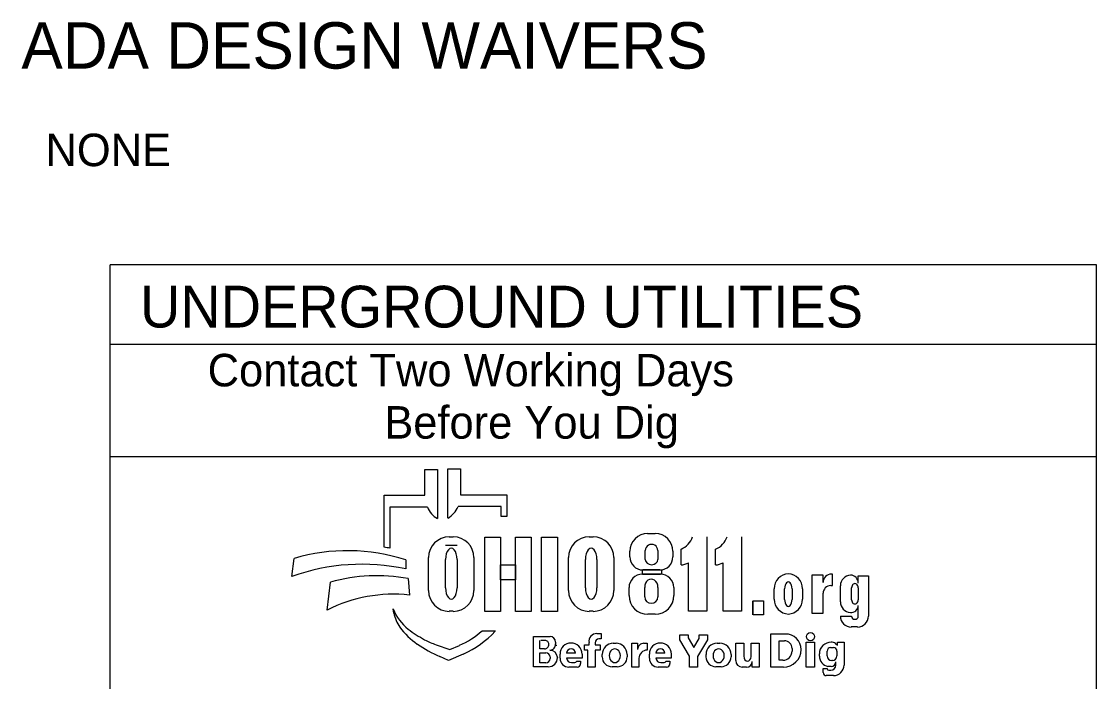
# Model space of a CAD drawing. Extents: x -31.7 to 34, y 0 to 22.
# Drawn here: x -31.252 to -26.619, y 2.686 to 5.529 of the extents above; entities that cross this region are included whole.
import ezdxf

# ---------------------------------------------------------------- set-up
doc = ezdxf.new("R2010")
doc.units = 0
doc.layers.add('SH_Data', color=7, linetype='Continuous')
doc.layers.add('SH_Text', color=7, linetype='Continuous')

msp = doc.modelspace()

# ---------------------------------------------------------------- linework, layer by layer
at = {"layer": 'SH_Data'}
for p, q in [((-30.8694, 2.1428), (-30.8694, 4.4803)), ((-26.6194, 4.4803), (-30.8694, 4.4803)), ((-26.6194, 2.1428), (-26.6194, 4.4803)), ((-30.8694, 4.1387), (-26.6194, 4.1387)), ((-30.8694, 3.6553), (-26.6194, 3.6553))]:
    msp.add_line(p, q, dxfattribs=at)
at = {"layer": 'SH_Text'}
for p, q in [((-29.5133, 3.4883), (-29.5133, 3.5998)), ((-29.5133, 3.5998), (-29.4597, 3.5998)), ((-29.4597, 3.5998), (-29.4597, 3.3877)), ((-29.414, 3.39), (-29.414, 3.6021)), ((-29.414, 3.6021), (-29.3604, 3.6021)), ((-29.3604, 3.6021), (-29.3604, 3.4906)), ((-29.6893, 3.2644), (-29.6893, 3.4883)), ((-29.6893, 3.4883), (-29.5133, 3.4883)), ((-29.3604, 3.4906), (-29.1611, 3.4906)), ((-29.1611, 3.4906), (-29.1611, 3.3968)), ((-29.664, 3.4369), (-29.664, 3.26)), ((-29.5029, 3.4369), (-29.664, 3.4369)), ((-29.1844, 3.4392), (-29.3708, 3.4392)), ((-29.1844, 3.3968), (-29.1844, 3.4392)), ((-29.1611, 3.3968), (-29.1844, 3.3968)), ((-29.4083, 3.3091), (-29.3918, 3.3091)), ((-28.8053, 3.3091), (-28.7888, 3.3091)), ((-28.5538, 3.3231), (-28.521, 3.3231)), ((-28.2982, 3.3087), (-28.2982, 2.9887)), ((-28.1494, 3.3087), (-28.1494, 2.9887)), ((-29.3751, 3.2721), (-29.4249, 3.2721)), ((-28.6301, 3.2225), (-28.6301, 3.2468)), ((-28.5639, 3.2111), (-28.5639, 3.2504)), ((-28.5098, 3.2504), (-28.5098, 3.2111)), ((-28.4447, 3.2468), (-28.4447, 3.2225)), ((-28.4098, 3.188), (-28.4098, 3.2562)), ((-28.261, 3.188), (-28.261, 3.2562)), ((-30.0866, 3.1381), (-30.0773, 3.2162)), ((-29.596, 3.2097), (-29.596, 3.1709)), ((-29.4978, 3.0776), (-29.4978, 3.2196)), ((-29.4249, 3.089), (-29.4249, 3.2114)), ((-29.3751, 3.2114), (-29.3751, 3.089)), ((-29.3023, 3.2196), (-29.3023, 3.0776)), ((-28.8948, 3.0776), (-28.8948, 3.2196)), ((-28.8219, 3.089), (-28.8219, 3.2114)), ((-28.7721, 3.2114), (-28.7721, 3.089)), ((-28.6993, 3.2196), (-28.6993, 3.0776)), ((-28.3775, 2.9887), (-28.3775, 3.1973)), ((-28.2287, 2.9887), (-28.2287, 3.1973)), ((-28.5007, 3.1665), (-28.5741, 3.1665)), ((-29.9348, 2.9936), (-29.9201, 3.1137)), ((-29.586, 3.1291), (-29.5798, 3.0582)), ((-28.5759, 3.1482), (-28.4986, 3.1482)), ((-27.7975, 3.1436), (-27.8464, 3.1436)), ((-27.8464, 3.1436), (-27.8464, 2.9806)), ((-27.7975, 3.112), (-27.7975, 3.1436)), ((-27.7569, 3.1487), (-27.7608, 3.1487)), ((-27.7569, 3.0989), (-27.7569, 3.1487)), ((-27.646, 3.1094), (-27.646, 3.1404)), ((-27.646, 3.1404), (-27.6025, 3.1404)), ((-27.6025, 3.1404), (-27.6025, 2.9675)), ((-28.6338, 3.0563), (-28.6338, 3.0903)), ((-28.5663, 3.0503), (-28.5663, 3.0912)), ((-28.5094, 3.0912), (-28.5094, 3.0503)), ((-28.4407, 3.0903), (-28.4407, 3.0563)), ((-28.0084, 3.0404), (-28.0084, 3.0858)), ((-27.9634, 3.0396), (-27.9634, 3.0858)), ((-27.9312, 3.0858), (-27.9312, 3.0396)), ((-27.8862, 3.0858), (-27.8862, 3.0404)), ((-27.7975, 2.9806), (-27.7975, 3.0659)), ((-27.7646, 3.0989), (-27.7569, 3.0989)), ((-27.7229, 3.029), (-27.7229, 3.0986)), ((-27.6746, 3.0383), (-27.6746, 3.0893)), ((-27.646, 3.0893), (-27.646, 3.0383)), ((-28.1013, 3.0337), (-28.1013, 2.9737)), ((-27.646, 2.9675), (-27.646, 3.0139)), ((-29.6471, 2.9807), (-29.6502, 2.9986)), ((-29.3918, 2.9882), (-29.4083, 2.9882)), ((-28.7888, 2.9882), (-28.8053, 2.9882)), ((-28.5216, 2.9753), (-28.5528, 2.9753)), ((-28.2982, 2.9887), (-28.3775, 2.9887)), ((-28.1494, 2.9887), (-28.2287, 2.9887)), ((-27.8464, 2.9806), (-27.7975, 2.9806)), ((-27.7229, 2.9675), (-27.6746, 2.9675)), ((-27.6492, 2.9208), (-27.6762, 2.9208)), ((-29.2668, 2.9048), (-29.2094, 2.9048)), ((-29.0455, 2.749), (-29.0455, 2.8798)), ((-29.0455, 2.8798), (-28.9744, 2.8798)), ((-28.773, 2.8926), (-28.7535, 2.8926)), ((-28.7535, 2.8926), (-28.7535, 2.8696)), ((-28.415, 2.887), (-28.3791, 2.887)), ((-28.415, 2.8655), (-28.415, 2.887)), ((-28.3791, 2.887), (-28.3791, 2.8734)), ((-28.3791, 2.8734), (-28.355, 2.832)), ((-28.3318, 2.8719), (-28.3318, 2.887)), ((-28.3318, 2.887), (-28.296, 2.887)), ((-28.296, 2.887), (-28.296, 2.8655)), ((-28.0225, 2.8906), (-27.9602, 2.8906)), ((-28.0225, 2.7478), (-28.0225, 2.8906)), ((-29.4653, 2.8444), (-29.4058, 2.8239)), ((-29.4058, 2.8239), (-29.3648, 2.8417)), ((-29.0176, 2.8263), (-29.0176, 2.8632)), ((-28.9982, 2.8263), (-29.0176, 2.8263)), ((-28.9924, 2.8632), (-29.0136, 2.8632)), ((-28.9506, 2.856), (-28.9506, 2.8481)), ((-28.8256, 2.8212), (-28.8256, 2.8442)), ((-28.8256, 2.8442), (-28.8062, 2.8442)), ((-28.8062, 2.8442), (-28.8062, 2.8546)), ((-28.7801, 2.8526), (-28.7801, 2.8442)), ((-28.7801, 2.8442), (-28.7586, 2.8442)), ((-28.7535, 2.8691), (-28.7637, 2.8691)), ((-28.7586, 2.8442), (-28.7586, 2.8212)), ((-28.7017, 2.8508), (-28.6896, 2.8508)), ((-28.6215, 2.7478), (-28.6215, 2.8505)), ((-28.6215, 2.8505), (-28.5969, 2.8505)), ((-28.5969, 2.8505), (-28.5969, 2.8237)), ((-28.5697, 2.8505), (-28.5558, 2.8505)), ((-28.5558, 2.8505), (-28.5558, 2.8209)), ((-28.3737, 2.7946), (-28.415, 2.8655)), ((-28.355, 2.832), (-28.3318, 2.8719)), ((-28.296, 2.8655), (-28.3381, 2.7932)), ((-28.2543, 2.8508), (-28.2422, 2.8508)), ((-28.1742, 2.8508), (-28.1394, 2.8508)), ((-28.1742, 2.7762), (-28.1742, 2.8508)), ((-28.1394, 2.8508), (-28.1394, 2.7954)), ((-28.108, 2.7938), (-28.108, 2.8508)), ((-28.108, 2.8508), (-28.0733, 2.8508)), ((-28.0733, 2.8508), (-28.0733, 2.7478)), ((-27.9865, 2.7773), (-27.9865, 2.8613)), ((-27.9865, 2.8613), (-27.9641, 2.8613)), ((-27.9314, 2.8286), (-27.9314, 2.8168)), ((-27.8699, 2.8549), (-27.8343, 2.8549)), ((-27.8699, 2.7478), (-27.8699, 2.8549)), ((-27.8343, 2.8549), (-27.8343, 2.7478)), ((-27.7653, 2.8319), (-27.7525, 2.8319)), ((-27.7447, 2.8493), (-27.7362, 2.8427)), ((-27.7362, 2.8553), (-27.7074, 2.8553)), ((-27.7362, 2.8427), (-27.7362, 2.8553)), ((-27.7362, 2.8553), (-27.7074, 2.8553)), ((-27.7074, 2.8553), (-27.7074, 2.7567)), ((-29.4119, 2.7769), (-29.4492, 2.7934)), ((-29.3486, 2.8044), (-29.4119, 2.7769)), ((-29.0176, 2.7669), (-29.0176, 2.8097)), ((-29.0176, 2.8097), (-28.992, 2.8097)), ((-28.9739, 2.7916), (-28.9739, 2.7853)), ((-28.9426, 2.7887), (-28.9426, 2.7884)), ((-28.931, 2.7858), (-28.931, 2.8042)), ((-28.8644, 2.8082), (-28.9029, 2.8082)), ((-28.8365, 2.7866), (-28.9029, 2.7866)), ((-28.8365, 2.8042), (-28.8365, 2.7866)), ((-28.8107, 2.8212), (-28.8256, 2.8212)), ((-28.8107, 2.7478), (-28.8107, 2.8212)), ((-28.7586, 2.8212), (-28.7801, 2.8212)), ((-28.7801, 2.8212), (-28.7801, 2.7478)), ((-28.7496, 2.7922), (-28.7496, 2.8029)), ((-28.6418, 2.8029), (-28.6418, 2.7922)), ((-28.591, 2.786), (-28.591, 2.7478)), ((-28.5461, 2.7858), (-28.5461, 2.8042)), ((-28.4795, 2.8082), (-28.518, 2.8082)), ((-28.4516, 2.7866), (-28.518, 2.7866)), ((-28.4516, 2.8042), (-28.4516, 2.7866)), ((-28.3737, 2.7478), (-28.3737, 2.7946)), ((-28.3381, 2.7932), (-28.3381, 2.7478)), ((-28.3021, 2.7922), (-28.3021, 2.8029)), ((-28.1944, 2.8029), (-28.1944, 2.7922)), ((-27.8134, 2.7953), (-27.8134, 2.8054)), ((-27.7799, 2.7961), (-27.7799, 2.8173)), ((-27.7379, 2.8173), (-27.7379, 2.7961)), ((-28.9819, 2.749), (-29.0455, 2.749)), ((-28.9923, 2.7669), (-29.0176, 2.7669)), ((-28.8576, 2.7478), (-28.893, 2.7478)), ((-28.882, 2.7673), (-28.8678, 2.7673)), ((-28.8593, 2.7729), (-28.8424, 2.7729)), ((-28.8424, 2.7729), (-28.8424, 2.7631)), ((-28.7801, 2.7478), (-28.8107, 2.7478)), ((-28.6846, 2.7494), (-28.7068, 2.7494)), ((-28.591, 2.7478), (-28.6215, 2.7478)), ((-28.4727, 2.7478), (-28.5081, 2.7478)), ((-28.497, 2.7673), (-28.4829, 2.7673)), ((-28.4744, 2.7729), (-28.4575, 2.7729)), ((-28.4575, 2.7729), (-28.4575, 2.7631)), ((-28.3381, 2.7478), (-28.3737, 2.7478)), ((-28.2372, 2.7494), (-28.2594, 2.7494)), ((-28.127, 2.7478), (-28.1458, 2.7478)), ((-28.1029, 2.7478), (-28.1029, 2.7719)), ((-28.0733, 2.7478), (-28.1029, 2.7478)), ((-27.9689, 2.7478), (-28.0225, 2.7478)), ((-27.9709, 2.7773), (-27.9865, 2.7773)), ((-27.8343, 2.7478), (-27.8699, 2.7478)), ((-27.7968, 2.7245), (-27.7968, 2.7415)), ((-27.7968, 2.7415), (-27.7799, 2.7415)), ((-27.7634, 2.7506), (-27.777, 2.7506)), ((-27.7731, 2.7345), (-27.7642, 2.7345)), ((-27.7572, 2.7768), (-27.7606, 2.7768)), ((-27.743, 2.7557), (-27.743, 2.7711)), ((-27.7527, 2.7114), (-27.7837, 2.7114))]:
    msp.add_line(p, q, dxfattribs=at)
for points in [[(-29.2559, 3.3081), (-29.1879, 3.3081), (-29.1879, 2.9881), (-29.2559, 2.9881)], [(-29.1238, 3.3081), (-29.0558, 3.3081), (-29.0558, 2.9881), (-29.1238, 2.9881)], [(-29.0104, 3.3081), (-28.9417, 3.3081), (-28.9417, 2.9881), (-29.0104, 2.9881)], [(-29.1879, 3.1882), (-29.1238, 3.1882), (-29.1238, 3.1242), (-29.1879, 3.1242)], [(-28.5762, 3.1665), (-28.4945, 3.1665), (-28.4945, 3.1481), (-28.5762, 3.1481)], [(-28.0989, 3.0337), (-28.0548, 3.0337), (-28.0548, 2.9737), (-28.0989, 2.9737)]]:
    msp.add_lwpolyline(points, close=True, dxfattribs=at)
msp.add_circle((-27.8517, 2.8793), 0.0177, dxfattribs=at)
for centre, radius, start, end in [((-29.4116, 3.4736), 0.0985, 201.9296, 240.7469), ((-29.4621, 3.476), 0.0985, 299.2531, 338.0704), ((-29.4083, 3.2196), 0.0895, 90, 180), ((-29.3918, 3.2196), 0.0895, 0, 90), ((-28.8053, 3.2196), 0.0895, 90, 180), ((-28.7888, 3.2196), 0.0895, 0, 90), ((-28.5538, 3.2468), 0.0763, 90, 180), ((-28.521, 3.2468), 0.0763, 0, 90), ((-28.4438, 3.3379), 0.0885, 292.5572, 340.7355), ((-28.2949, 3.3379), 0.0885, 292.5572, 340.7355), ((-29.8472, 2.4302), 0.8191, 72.1402, 106.3144), ((-29.8174, 2.4554), 0.8191, 79.2074, 81.0007), ((-28.5741, 3.2225), 0.056, 180, 270), ((-28.5007, 3.2225), 0.056, 270, 0), ((-28.4178, 3.2761), 0.0885, 275.1733, 297.0931), ((-28.2689, 3.2761), 0.0885, 275.1733, 297.0931), ((-29.7841, 2.2991), 0.8919, 77.8238, 109.8274), ((-29.7202, 2.4094), 0.7322, 79.44, 105.8467), ((-28.5759, 3.0903), 0.0579, 90, 180), ((-28.4986, 3.0903), 0.0579, 0, 90), ((-27.9444, 3.0858), 0.064, 92.5886, 180), ((-27.9502, 3.0858), 0.064, 0, 87.4114), ((-27.7608, 3.112), 0.0367, 90, 180), ((-27.677, 3.0986), 0.0459, 92.6865, 180), ((-27.6811, 3.1094), 0.0351, 0, 86.9262), ((-29.6482, 2.4262), 0.6357, 83.8248, 116.8021), ((-29.4083, 3.0776), 0.0895, 180, 270), ((-29.3918, 3.0776), 0.0895, 270, 0), ((-28.8053, 3.0776), 0.0895, 180, 270), ((-28.7888, 3.0776), 0.0895, 270, 0), ((-27.7646, 3.0659), 0.033, 90, 180), ((-28.5528, 3.0563), 0.081, 180, 270), ((-28.5216, 3.0563), 0.081, 270, 0), ((-27.9444, 3.0404), 0.064, 180, 267.4114), ((-27.9502, 3.0404), 0.064, 272.5886, 0), ((-27.6766, 3.029), 0.0463, 180, 265.7132), ((-27.6773, 3.0139), 0.0313, 264.7825, 0), ((-29.4628, 3.0707), 0.2008, 201.0457, 232.5314), ((-29.5058, 3.0048), 0.1433, 189.6817, 216.0884), ((-27.6762, 2.9675), 0.0468, 180, 270), ((-27.6492, 2.9675), 0.0468, 270, 0), ((-29.3722, 3.1022), 0.3088, 216.0884, 235.7167), ((-29.2703, 3.3219), 0.5173, 232.5314, 241.794), ((-29.5082, 3.1722), 0.3602, 293.4582, 312.0712), ((-29.5082, 3.1722), 0.401, 293.4582, 317.8286), ((-28.9744, 2.856), 0.0238, 0, 90), ((-28.773, 2.859), 0.0335, 90, 187.5187), ((-27.9602, 2.8223), 0.0682, 0.9944, 90), ((-29.2056, 3.3465), 0.6044, 235.7167, 246.2325), ((-29.3554, 3.1631), 0.3371, 241.794, 250.9821), ((-28.9982, 2.845), 0.0187, 270, 2.0582), ((-28.9963, 2.8463), 0.0169, 357.8325, 90), ((-28.9748, 2.8453), 0.0243, 270, 6.6529), ((-28.9642, 2.8438), 0.0175, 347.4023, 0), ((-28.8837, 2.8042), 0.0473, 0, 180), ((-28.8837, 2.8072), 0.0193, 2.9632, 177.0368), ((-28.7637, 2.8526), 0.0165, 90, 180), ((-28.7017, 2.8029), 0.0478, 90, 180), ((-28.6896, 2.8029), 0.0478, 0, 90), ((-28.5701, 2.8237), 0.0269, 89.2449, 180), ((-28.4988, 2.8042), 0.0473, 0, 180), ((-28.4988, 2.8072), 0.0193, 2.9632, 177.0368), ((-28.2543, 2.8029), 0.0478, 90, 180), ((-28.2422, 2.8029), 0.0478, 0, 90), ((-27.9641, 2.8286), 0.0327, 0, 90), ((-27.7635, 2.8054), 0.0499, 89.0934, 180), ((-27.7653, 2.8173), 0.0146, 90, 180), ((-27.7621, 2.827), 0.0283, 52.1415, 91.2046), ((-27.7525, 2.8173), 0.0146, 0, 90), ((-28.9923, 2.7853), 0.0184, 270, 0), ((-28.992, 2.7916), 0.0181, 0, 90), ((-28.9819, 2.7884), 0.0393, 270, 0), ((-28.9747, 2.7889), 0.0321, 4.0748, 90), ((-28.9755, 2.7887), 0.033, 0, 11.7502), ((-28.893, 2.7858), 0.038, 180, 270), ((-28.882, 2.7883), 0.021, 184.827, 270), ((-28.7068, 2.7922), 0.0428, 180, 270), ((-28.6846, 2.7922), 0.0428, 270, 0), ((-28.5561, 2.786), 0.0349, 89.6033, 180), ((-28.5081, 2.7858), 0.038, 180, 270), ((-28.497, 2.7883), 0.021, 184.827, 270), ((-28.2594, 2.7922), 0.0428, 180, 270), ((-28.2372, 2.7922), 0.0428, 270, 0), ((-27.9709, 2.8168), 0.0395, 270, 0), ((-27.9689, 2.8248), 0.0769, 270, 359.0635), ((-27.7677, 2.7953), 0.0457, 180, 258.2203), ((-27.7606, 2.7961), 0.0193, 180, 270), ((-27.7572, 2.7961), 0.0193, 270, 0), ((-28.8678, 2.7767), 0.00938, 270, 335.9979), ((-28.8576, 2.7631), 0.0152, 270, 0), ((-28.4829, 2.7767), 0.00938, 270, 335.9979), ((-28.4727, 2.7631), 0.0152, 270, 0), ((-28.1458, 2.7762), 0.0284, 180, 270), ((-28.127, 2.7719), 0.024, 270, 0), ((-27.7731, 2.7413), 0.00682, 180, 270), ((-27.7642, 2.7557), 0.0212, 270, 0), ((-27.7634, 2.771), 0.0203, 270, 0), ((-27.7527, 2.7567), 0.0453, 270, 0), ((-27.7837, 2.7245), 0.0131, 180, 270)]:
    msp.add_arc(centre, radius, start, end, dxfattribs=at)
for centre, major_axis, ratio, start_param, end_param in [((-29.4, 3.2114), (0, 0.0484), 0.514403, 4.712389, 7.853982), ((-28.797, 3.2114), (0, 0.0484), 0.514403, 4.712389, 7.853982), ((-28.5368, 3.2504), (0.0271, 0), 0.969373, 0, 3.141593), ((-28.5368, 3.2111), (0.0271, 0), 0.818453, 3.141593, 6.283185), ((-28.5379, 3.0912), (0, 0.0358), 0.794529, 4.712389, 7.853982), ((-27.9473, 3.0858), (0, 0.0291), 0.553236, 4.712389, 7.853982), ((-27.6603, 3.0893), (0, 0.0184), 0.777179, 4.712389, 7.853982), ((-29.4, 3.089), (0, 0.0484), 0.514403, 1.570796, 4.712389), ((-28.797, 3.089), (0, 0.0484), 0.514403, 1.570796, 4.712389), ((-28.5379, 3.0503), (0.0284, 0), 0.959837, 3.141593, 6.283185), ((-27.9473, 3.0396), (0, 0.0308), 0.522014, 1.570796, 4.712389), ((-27.6603, 3.0383), (0, 0.0184), 0.777179, 1.570796, 4.712389), ((-27.6603, 2.9675), (0.0143, 0), 0.959012, 3.141593, 6.283185), ((-28.6952, 2.7976), (0, 0.029), 0.832186, 4.712389, 7.853982), ((-28.2478, 2.7976), (0, 0.029), 0.832186, 4.712389, 7.853982), ((-28.6952, 2.7976), (0, 0.0302), 0.797287, 1.570796, 4.712389), ((-28.2478, 2.7976), (0, 0.0302), 0.797287, 1.570796, 4.712389), ((-28.1237, 2.7962), (-0.0011, 0.0231), 0.679042, 1.570796, 4.575961)]:
    msp.add_ellipse(centre, major_axis=major_axis, ratio=ratio, start_param=start_param, end_param=end_param, dxfattribs=at)

# ---------------------------------------------------------------- texts
for s, height, p in [('ADA DESIGN WAIVERS', 0.2, (-31.2525, 5.3256)), ('  NONE', 0.14, (-31.2525, 4.9056)), ('UNDERGROUND UTILITIES', 0.18, (-30.7412, 4.2106)), ('Contact Two Working Days', 0.14, (-30.4497, 3.9571)), ('Before You Dig', 0.14, (-29.6885, 3.7321))]:
    msp.add_text(s, height=height, dxfattribs=at).set_placement(p)

doc.saveas('drawing.dxf')
